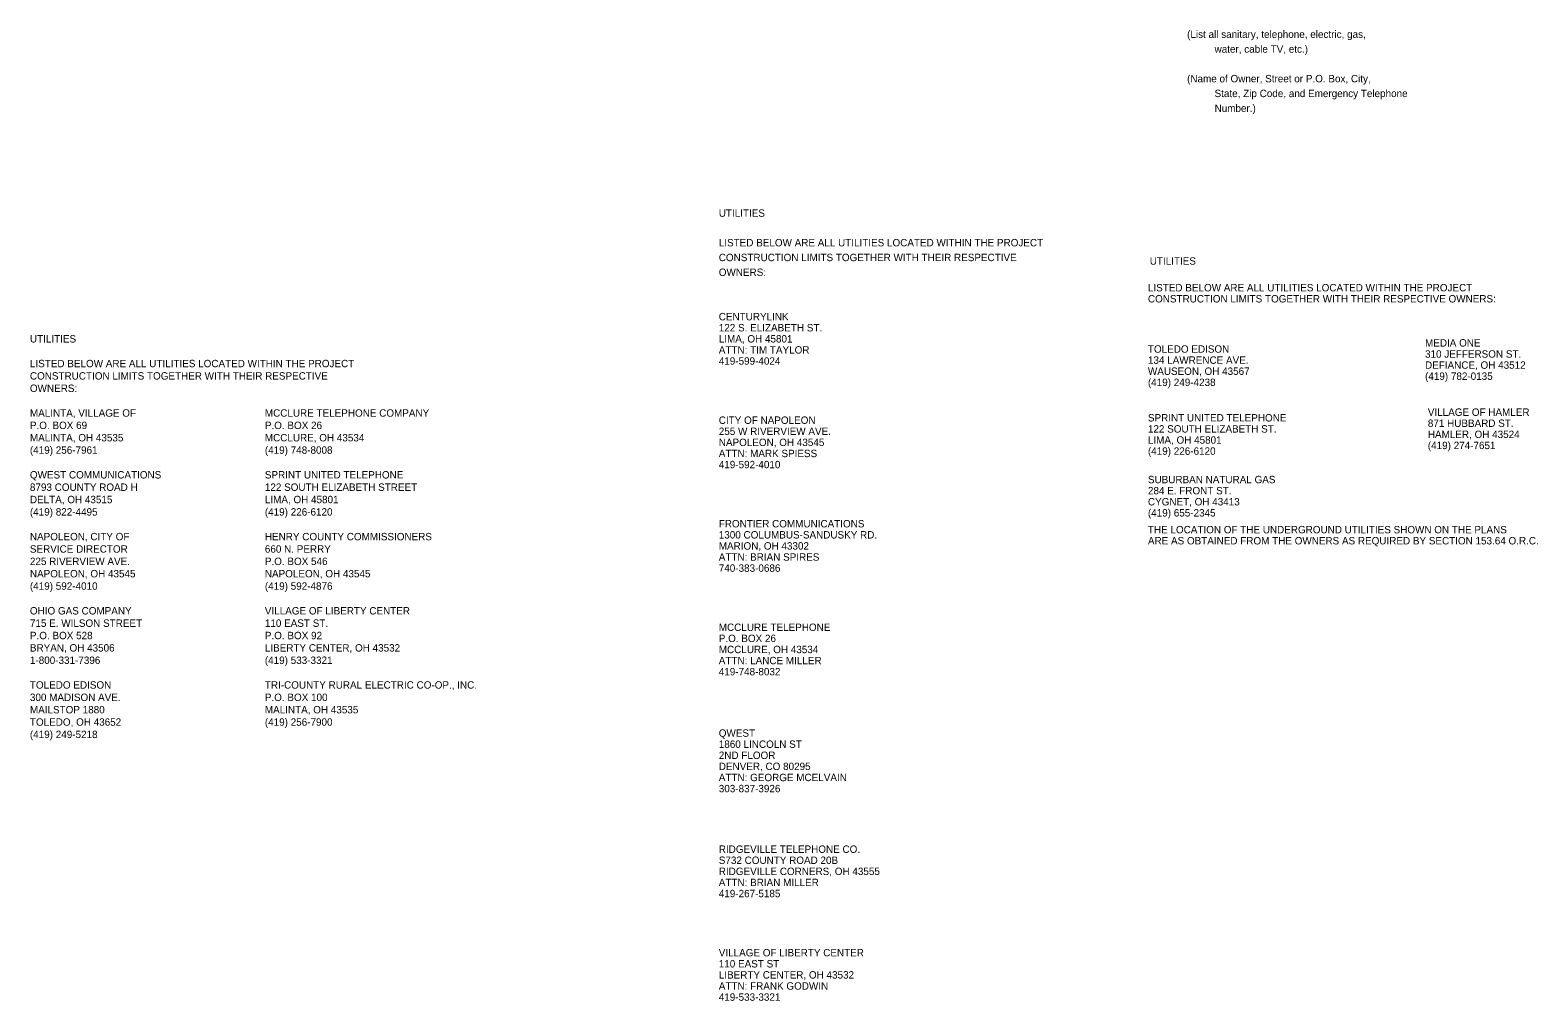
# Model space of a CAD drawing. Extents: x -28.8 to 41.7, y 0 to 25.4.
# Drawn here: x -28.76 to -0.23, y 4.31 to 22.69 of the extents above; entities that cross this region are included whole.
import ezdxf

# ---------------------------------------------------------------- set-up
doc = ezdxf.new("R2010")
doc.units = 0
for name, color, linetype in [('Default', 7, 'Continuous'), ('SH_Text', 7, 'Continuous'), ('TX_P_Misc', 7, 'Continuous')]:
    doc.layers.add(name, color=color, linetype=linetype)

msp = doc.modelspace()

# ---------------------------------------------------------------- texts
at = {"layer": 'Default'}
for s, p in [('UTILITIES', (-7.575, 18.247)), ('LISTED BELOW ARE ALL UTILITIES LOCATED WITHIN THE PROJECT', (-7.61, 17.742)), ('CONSTRUCTION LIMITS TOGETHER WITH THEIR RESPECTIVE OWNERS:', (-7.61, 17.532)), ('UTILITIES', (-28.767, 16.774)), ('MEDIA ONE', (-2.366, 16.697)), ('TOLEDO EDISON', (-7.61, 16.581)), ('310 JEFFERSON ST.', (-2.366, 16.487)), ('LISTED BELOW ARE ALL UTILITIES LOCATED WITHIN THE PROJECT', (-28.767, 16.306)), ('WAUSEON, OH 43567', (-7.61, 16.161)), ('134 LAWRENCE AVE.', (-7.61, 16.371)), ('DEFIANCE, OH 43512', (-2.366, 16.277)), ('OWNERS:', (-28.767, 15.838)), ('CONSTRUCTION LIMITS TOGETHER WITH THEIR RESPECTIVE', (-28.767, 16.072)), ('(419) 249-4238', (-7.61, 15.951)), ('(419) 782-0135', (-2.366, 16.067)), ('MALINTA, VILLAGE OF', (-28.767, 15.37)), ('MCCLURE TELEPHONE COMPANY', (-24.321, 15.37)), ('SPRINT UNITED TELEPHONE', (-7.61, 15.279)), ('VILLAGE OF HAMLER', (-2.313, 15.386)), ('P.O. BOX 69', (-28.767, 15.136)), ('P.O. BOX 26', (-24.321, 15.136)), ('122 SOUTH ELIZABETH ST.', (-7.61, 15.069)), ('871 HUBBARD ST.', (-2.313, 15.176)), ('MALINTA, OH 43535', (-28.767, 14.902)), ('MCCLURE, OH 43534', (-24.321, 14.902)), ('LIMA, OH 45801', (-7.61, 14.859)), ('(419) 274-7651', (-2.313, 14.756)), ('HAMLER, OH 43524', (-2.313, 14.966)), ('(419) 256-7961', (-28.767, 14.668)), ('(419) 748-8008', (-24.321, 14.668)), ('(419) 226-6120', (-7.61, 14.649)), ('QWEST COMMUNICATIONS', (-28.767, 14.2)), ('SPRINT UNITED TELEPHONE', (-24.321, 14.2)), ('8793 COUNTY ROAD H', (-28.767, 13.966)), ('122 SOUTH ELIZABETH STREET', (-24.321, 13.966)), ('SUBURBAN NATURAL GAS', (-7.61, 14.11)), ('284 E. FRONT ST.', (-7.61, 13.9)), ('DELTA, OH 43515', (-28.767, 13.732)), ('LIMA, OH 45801', (-24.321, 13.732)), ('CYGNET, OH 43413', (-7.61, 13.69)), ('(419) 822-4495', (-28.767, 13.498)), ('(419) 226-6120', (-24.321, 13.498)), ('(419) 655-2345', (-7.61, 13.48)), ('NAPOLEON, CITY OF', (-28.767, 13.03)), ('HENRY COUNTY COMMISSIONERS', (-24.321, 13.03)), ('THE LOCATION OF THE UNDERGROUND UTILITIES SHOWN ON THE PLANS ', (-7.61, 13.162)), ('SERVICE DIRECTOR', (-28.767, 12.796)), ('660 N. PERRY', (-24.321, 12.796)), ('ARE AS OBTAINED FROM THE OWNERS AS REQUIRED BY SECTION 153.64 O.R.C.', (-7.61, 12.952)), ('225 RIVERVIEW AVE.', (-28.767, 12.562)), ('P.O. BOX 546', (-24.321, 12.562)), ('NAPOLEON, OH 43545', (-28.767, 12.328)), ('NAPOLEON, OH 43545', (-24.321, 12.328)), ('(419) 592-4010', (-28.767, 12.094)), ('(419) 592-4876', (-24.321, 12.094)), ('OHIO GAS COMPANY', (-28.767, 11.626)), ('VILLAGE OF LIBERTY CENTER', (-24.321, 11.626)), ('715 E. WILSON STREET', (-28.767, 11.392)), ('110 EAST ST.', (-24.321, 11.392)), ('P.O. BOX 528', (-28.767, 11.158)), ('P.O. BOX 92', (-24.321, 11.158)), ('BRYAN, OH 43506', (-28.767, 10.924)), ('LIBERTY CENTER, OH 43532', (-24.321, 10.924)), ('1-800-331-7396', (-28.767, 10.69)), ('(419) 533-3321', (-24.321, 10.69)), ('TOLEDO EDISON', (-28.767, 10.222)), ('TRI-COUNTY RURAL ELECTRIC CO-OP., INC.', (-24.321, 10.222)), ('300 MADISON AVE.', (-28.767, 9.988)), ('P.O. BOX 100', (-24.321, 9.988)), ('MAILSTOP 1880', (-28.767, 9.754)), ('MALINTA, OH 43535', (-24.321, 9.754)), ('TOLEDO, OH 43652', (-28.767, 9.52)), ('(419) 249-5218', (-28.767, 9.286)), ('(419) 256-7900', (-24.321, 9.52))]:
    msp.add_text(s, height=0.14, dxfattribs=at).set_placement(p)
at = {"layer": 'SH_Text'}
for s, p in [('    (List all sanitary, telephone, electric, gas,', (-7.077, 22.539)), ('              water, cable TV, etc.)', (-7.077, 22.259)), ('    (Name of Owner, Street or P.O. Box, City,', (-7.077, 21.699)), ('              State, Zip Code, and Emergency Telephone', (-7.077, 21.419)), ('              Number.)', (-7.077, 21.139)), ('CENTURYLINK', (-15.731, 17.194)), ('122 S. ELIZABETH ST.', (-15.731, 16.984)), ('LIMA, OH 45801', (-15.731, 16.774)), ('ATTN: TIM TAYLOR', (-15.731, 16.564)), ('419-599-4024', (-15.731, 16.354)), ('CITY OF NAPOLEON', (-15.731, 15.234)), ('255 W RIVERVIEW AVE.', (-15.731, 15.024)), ('NAPOLEON, OH 43545', (-15.731, 14.814)), ('ATTN: MARK SPIESS', (-15.731, 14.604)), ('419-592-4010', (-15.731, 14.394)), ('FRONTIER COMMUNICATIONS', (-15.731, 13.274)), ('1300 COLUMBUS-SANDUSKY RD. ', (-15.731, 13.064)), ('MARION, OH 43302', (-15.731, 12.854)), ('ATTN: BRIAN SPIRES ', (-15.731, 12.644)), ('740-383-0686', (-15.731, 12.434)), ('MCCLURE TELEPHONE', (-15.731, 11.314)), ('P.O. BOX 26 ', (-15.731, 11.104)), ('MCCLURE, OH 43534', (-15.731, 10.894)), ('ATTN: LANCE MILLER ', (-15.731, 10.684)), ('419-748-8032', (-15.731, 10.474)), ('QWEST', (-15.731, 9.311)), ('1860 LINCOLN ST', (-15.731, 9.101)), ('2ND FLOOR ', (-15.731, 8.891)), ('ATTN: GEORGE MCELVAIN ', (-15.731, 8.471)), ('DENVER, CO 80295 ', (-15.731, 8.681)), ('303-837-3926', (-15.731, 8.261)), ('RIDGEVILLE TELEPHONE CO.', (-15.731, 7.114)), ('S732 COUNTY ROAD 20B', (-15.731, 6.904)), ('ATTN: BRIAN MILLER', (-15.731, 6.484)), ('RIDGEVILLE CORNERS, OH 43555', (-15.731, 6.694)), ('419-267-5185', (-15.731, 6.274)), ('VILLAGE OF LIBERTY CENTER', (-15.731, 5.154)), ('110 EAST ST', (-15.731, 4.944)), ('LIBERTY CENTER, OH 43532 ', (-15.731, 4.734)), ('ATTN: FRANK GODWIN ', (-15.731, 4.524)), ('419-533-3321', (-15.731, 4.314))]:
    msp.add_text(s, height=0.14, dxfattribs=at).set_placement(p)
at = {"layer": 'TX_P_Misc'}
for s, p in [('UTILITIES', (-15.731, 19.154)), ('LISTED BELOW ARE ALL UTILITIES LOCATED WITHIN THE PROJECT', (-15.731, 18.594)), ('CONSTRUCTION LIMITS TOGETHER WITH THEIR RESPECTIVE', (-15.731, 18.314)), ('OWNERS:', (-15.731, 18.034))]:
    msp.add_text(s, height=0.14, dxfattribs=at).set_placement(p)

doc.saveas('drawing.dxf')
